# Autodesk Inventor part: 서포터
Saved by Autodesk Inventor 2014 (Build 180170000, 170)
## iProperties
Created: 2025-02
Part Number: 서포터
Material: 일반
Document SubType Name: Modeling
Designer: dg
Density: 1 g/cm^3
Appearance: 기본값
Author: dg
Author: jhkim
Creation Date: 2025-02-05
Sending System: Autodesk Inventor 2025
Preprocessor: ST-DEVELOPER v20
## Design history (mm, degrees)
node "서포터1"
node "솔리드1"
node "기준1"
